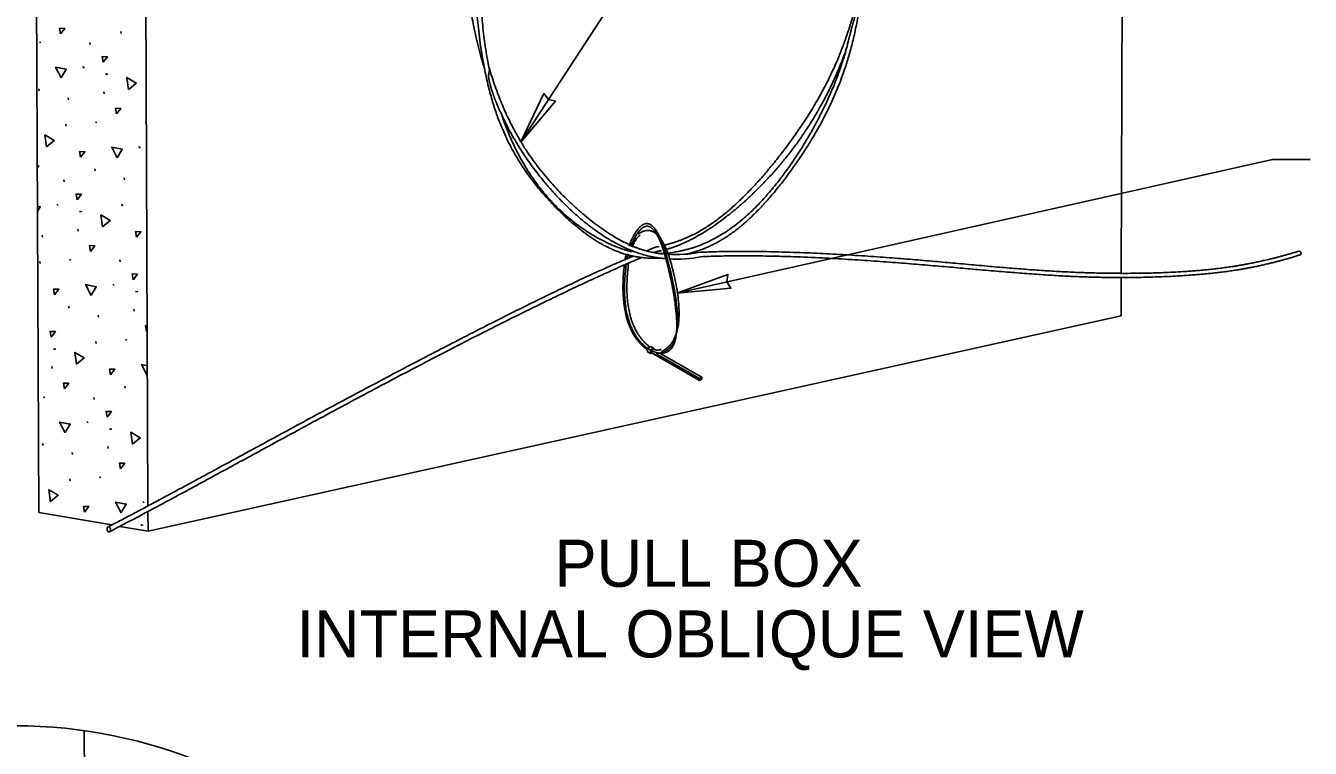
# Model space of a CAD drawing. Extents: x 99862 to 103151, y 100000 to 105076.
# Drawn here: x 101250 to 101795, y 101383 to 101690 of the extents above; entities that cross this region are included whole.
import ezdxf

# ---------------------------------------------------------------- set-up
doc = ezdxf.new("R2010")
doc.units = 0
for name, color, linetype in [('Level 1', 7, 'Continuous'), ('Level 15', 7, 'Continuous'), ('Level 17', 7, 'Continuous'), ('Level 2', 7, 'Continuous'), ('Level 20', 7, 'Continuous'), ('Level 30', 7, 'Continuous'), ('Level 9', 7, 'Continuous')]:
    doc.layers.add(name, color=color, linetype=linetype)

msp = doc.modelspace()

# ---------------------------------------------------------------- linework, layer by layer
at = {"layer": 'Level 1'}
msp.add_line((101274.61, 101299.42), (101274.56, 101390.36), dxfattribs=at)
msp.add_circle((101245.08, 101183.57), 208.77, dxfattribs=at)
at = {"layer": 'Level 15'}
for p, q in [((101459.82, 101640.12), (101521.88, 101735.47)), ((101779.33, 101632.96), (101526.3, 101576.13)), ((101795.33, 101632.96), (101779.33, 101632.96))]:
    msp.add_line(p, q, dxfattribs=at)
for points in [[(101459.82, 101640.12), (101469.77, 101660.88), (101471.69, 101658.36), (101474.77, 101657.62)], [(101526.3, 101576.13), (101549.23, 101578.22), (101547.55, 101580.9), (101547.92, 101584.05)]]:
    msp.add_lwpolyline(points, close=True, dxfattribs=at)
at = {"layer": 'Level 17'}
for p, q in [((101510.64, 101601.75), (101509.64, 101601.18)), ((101510.1, 101600.5), (101510.1, 101600.5)), ((101513.79, 101552.75), (101515.11, 101553.52)), ((101513.79, 101551.22), (101513.79, 101552.75)), ((101515.11, 101551.99), (101513.79, 101552.75)), ((101515.11, 101550.46), (101513.79, 101551.22)), ((101516.44, 101552.75), (101515.11, 101553.52)), ((101515.11, 101551.99), (101516.44, 101552.75)), ((101515.11, 101550.46), (101515.11, 101551.99)), ((101515.61, 101550.74), (101515.11, 101550.46)), ((101515.28, 101551.74), (101516.27, 101552.32)), ((101515.28, 101550.93), (101515.28, 101551.74)), ((101535.83, 101539.07), (101515.28, 101550.93)), ((101516.44, 101552.75), (101516.44, 101552.25)), ((101535.83, 101539.83), (101517.28, 101550.54)), ((101536.82, 101540.41), (101518.8, 101550.81)), ((101519.58, 101551.18), (101520.58, 101551.75)), ((101535.83, 101539.83), (101536.82, 101540.41)), ((101535.83, 101539.07), (101535.83, 101539.83)), ((101536.82, 101539.64), (101535.83, 101539.07)), ((101536.82, 101540.41), (101536.82, 101539.64))]:
    msp.add_line(p, q, dxfattribs=at)
for points in [[(101524.12, 101583.06), (101515.87, 101620.3), (101505.88, 101596.21)], [(101523.48, 101583.22), (101515.98, 101618.07), (101506.62, 101595.94)], [(101510.6, 101600.76), (101508.62, 101599.29), (101507.29, 101595.71)], [(101525.11, 101583.63), (101519.91, 101607.11), (101510.64, 101601.75)], [(101505.22, 101594.41), (101505.18, 101594.28), (101505.14, 101594.14)], [(101505.95, 101594.14), (101505.93, 101594.06), (101505.9, 101593.98)], [(101506.7, 101593.88), (101506.69, 101593.85), (101506.68, 101593.82)], [(101503.96, 101588.23), (101500.87, 101561.65), (101513.79, 101551.87)], [(101504.77, 101588.56), (101501.33, 101562.09), (101513.79, 101552.63)], [(101504.65, 101592.31), (101504.44, 101591.4), (101504.27, 101590.43)], [(101505.74, 101588.97), (101502.45, 101562.83), (101514.69, 101553.27)], [(101505.41, 101592.15), (101505.25, 101591.48), (101505.12, 101590.78)], [(101506.24, 101591.98), (101506.16, 101591.58), (101506.08, 101591.17)], [(101515.28, 101551.74), (101531.72, 101544.62), (101523.48, 101583.22)], [(101517.28, 101550.54), (101531.39, 101550.49), (101524.12, 101583.06)], [(101520.58, 101551.75), (101530.9, 101557.71), (101525.11, 101583.63)], [(101516.27, 101552.32), (101518.02, 101551.56), (101519.63, 101552.24)]]:
    msp.add_open_spline(points, degree=2, dxfattribs=at)
at = {"layer": 'Level 2'}
for p, q in [((101252.49, 102058.09), (101255.28, 101482.88)), ((101301.58, 101485.66), (101299.24, 102058.35)), ((101715.7, 101831.46), (101715.03, 101584.19)), ((101715.02, 101582.43), (101714.98, 101566.54)), ((101714.98, 101566.54), (101301.63, 101475.03)), ((101301.63, 101475.03), (101301.59, 101483.33)), ((101286.23, 101477.64), (101255.28, 101482.88)), ((101301.63, 101475.03), (101289.63, 101477.06))]:
    msp.add_line(p, q, dxfattribs=at)
at = {"layer": 'Level 30'}
for points, degree in [([(101496.76, 101860.97), (101489.22, 101857.41), (101475.08, 101847.32), (101454.44, 101820.1), (101440.55, 101783.63), (101433.45, 101730.23), (101437.88, 101693.33), (101444.56, 101671.4)], 4), ([(101500.41, 101851.5), (101498.68, 101850.1), (101487.39, 101841.27), (101470.38, 101821.19), (101453.25, 101785.1), (101440.55, 101738.77), (101439.71, 101701.95), (101443.1, 101679.69)], 4), ([(101446.53, 101671.57), (101442.22, 101692.95), (101441.48, 101729.1), (101453.52, 101781.74), (101470.66, 101817.94), (101488.3, 101838.79), (101496.84, 101846.14), (101500.94, 101849.56)], 4), ([(101602.08, 101697.49), (101596.55, 101677.42), (101583.66, 101648.28), (101554.67, 101612.16), (101533.92, 101599.62), (101520.38, 101596.35)], 4), ([(101530.45, 101592.7), (101543.36, 101595.94), (101562.84, 101608.14), (101589.37, 101644.32), (101600.09, 101675.12), (101603.78, 101696.76)], 4), ([(101599.17, 101683.48), (101599.27, 101683.88), (101599.37, 101684.29), (101599.62, 101685.3), (101599.78, 101685.91), (101600.25, 101687.72), (101600.57, 101688.93), (101601.06, 101690.75), (101601.23, 101691.35), (101601.59, 101692.55), (101601.78, 101693.15), (101602.13, 101694.02), (101602.26, 101694.3), (101602.56, 101694.85), (101602.75, 101695.11), (101603.13, 101695.58), (101603.33, 101695.79), (101603.61, 101696.22), (101603.71, 101696.45), (101603.79, 101696.79), (101603.8, 101696.86), (101603.81, 101696.94)], 4), ([(101443.02, 101680.23), (101443.11, 101679.6), (101443.21, 101678.96), (101443.52, 101677.05), (101443.76, 101675.79), (101444.1, 101673.92), (101444.21, 101673.3), (101444.37, 101672.4), (101444.42, 101672.11), (101444.51, 101671.63), (101444.55, 101671.43), (101444.6, 101671.24)], 4), ([(101599.22, 101683.69), (101596.79, 101673.62), (101588.58, 101648.69), (101565.57, 101611.58), (101541.21, 101596.6), (101526.92, 101593.87)], 4), ([(101521.33, 101594.63), (101527.42, 101596.14), (101544.55, 101603.1), (101573.28, 101628.29), (101590.9, 101659.89), (101598, 101678.91)], 4), ([(101444.49, 101671.71), (101448.65, 101650.75), (101460.41, 101622.8), (101487.89, 101596.08), (101506.99, 101590.52), (101518.97, 101591.02)], 4), ([(101446.88, 101664.97), (101446.72, 101665.58), (101446.57, 101666.18), (101446.34, 101667.41), (101446.26, 101668.02), (101446.31, 101668.99), (101446.37, 101669.31), (101446.51, 101669.98), (101446.59, 101670.32), (101446.63, 101671), (101446.59, 101671.34), (101446.51, 101671.67)], 4), ([(101520.41, 101592.79), (101511.83, 101593.66), (101495.92, 101599.03), (101468.13, 101622.35), (101452.99, 101650.48), (101446.47, 101671.89)], 4), ([(101448.92, 101658.74), (101448.57, 101659.64), (101448.24, 101660.56), (101447.74, 101662.06), (101447.55, 101662.64), (101447.29, 101663.51), (101447.2, 101663.8), (101447.04, 101664.39), (101446.96, 101664.67), (101446.88, 101664.97)], 4), ([(101448.84, 101658.94), (101452.88, 101648.5), (101465.09, 101624.53), (101490.14, 101598.96), (101511.39, 101591.6), (101521.26, 101590.78)], 4), ([(101507.13, 101593.73), (101506.75, 101593.81), (101495.71, 101595.97), (101473.56, 101608.25), (101457.8, 101634.55), (101451.97, 101651.4)], 4), ([(101517.57, 101595.74), (101516.09, 101595.17), (101514.61, 101594.59), (101513.13, 101594.01)], 3), ([(101516.55, 101593.31), (101517.1, 101593.53), (101517.66, 101593.74), (101518.21, 101593.95)], 3), ([(101518.72, 101595.97), (101518.33, 101595.89), (101517.95, 101595.82), (101517.57, 101595.74)], 3), ([(101518.16, 101593.94), (101518.67, 101594.03), (101519.19, 101594.14), (101519.7, 101594.25)], 3), ([(101520.31, 101593), (101519.91, 101592.97), (101519.52, 101592.95), (101519.12, 101592.93)], 3), ([(101526.92, 101593.87), (101525.29, 101593.55), (101523.66, 101593.31), (101522.04, 101593.15)], 3), ([(101536.29, 101593.5), (101531.64, 101592.61), (101526.95, 101592.32), (101522.26, 101592.64)], 3), ([(101526.92, 101593.87), (101526.92, 101593.87), (101526.92, 101593.87)], 2), ([(101790.44, 101593.96), (101776.12, 101589.58), (101754.4, 101585.46), (101724.44, 101583.99), (101675.4, 101584.69), (101613.67, 101592.75), (101556.78, 101594.44), (101536.29, 101593.5)], 4), ([(101791.38, 101593.06), (101791.38, 101593.36), (101791.25, 101593.66), (101790.86, 101593.97), (101790.63, 101594.02), (101790.44, 101593.96)], 4), ([(101790.91, 101592.32), (101790.95, 101592.33), (101790.99, 101592.35), (101791.24, 101592.49), (101791.38, 101592.76), (101791.38, 101593.06)], 4), ([(101507.49, 101591.75), (101478.35, 101579.88), (101406.43, 101544.16), (101331.01, 101500.72), (101284.6, 101476.8)], 4), ([(101285.27, 101474.8), (101346.72, 101506.52), (101422.23, 101551.63), (101494.64, 101584.54), (101511.31, 101591.23)], 4), ([(101523.06, 101590.66), (101527.54, 101590.43), (101532.02, 101590.74), (101536.45, 101591.59)], 3), ([(101536.45, 101591.59), (101560.02, 101592.7), (101616.78, 101590.37), (101680.51, 101582.59), (101726.57, 101582.26), (101756.45, 101584.09), (101776.31, 101587.85), (101790.91, 101592.32)], 4), ([(101284.56, 101474.95), (101284.33, 101475.18), (101284.18, 101475.56), (101284.18, 101476.29), (101284.32, 101476.62), (101284.77, 101476.92), (101285.08, 101476.86), (101285.53, 101476.42), (101285.68, 101476.04), (101285.68, 101475.67)], 4), ([(101285.68, 101475.67), (101285.68, 101475.3), (101285.54, 101474.97), (101285.09, 101474.68), (101284.79, 101474.73), (101284.56, 101474.95)], 4)]:
    msp.add_open_spline(points, degree=degree, dxfattribs=at)
at = {"layer": 'Level 9'}
for p, q in [((101290.19, 101686.48), (101290.02, 101687.34)), ((101255.48, 101682.78), (101256.08, 101682.55)), ((101277.04, 101681.72), (101276.87, 101682.58)), ((101273.91, 101672.36), (101274.45, 101671.76)), ((101283.51, 101669.23), (101284.11, 101669)), ((101283.92, 101669.27), (101284.51, 101669.04)), ((101255.34, 101662.08), (101255.17, 101662.94)), ((101267.87, 101658.28), (101267.7, 101659.14)), ((101282.99, 101660.83), (101282.82, 101661.69)), ((101266.92, 101647.09), (101266.76, 101647.95)), ((101279.28, 101648.8), (101279.87, 101648.57)), ((101300.83, 101647.74), (101300.67, 101648.6)), ((101297.71, 101638.39), (101298.24, 101637.78)), ((101279.13, 101628.1), (101278.97, 101628.96)), ((101265.99, 101623.34), (101265.82, 101624.2)), ((101291.66, 101624.3), (101291.49, 101625.16)), ((101262.86, 101613.99), (101263.39, 101613.38)), ((101272.46, 101610.85), (101273.05, 101610.62)), ((101272.86, 101610.89), (101273.46, 101610.66)), ((101290.72, 101613.11), (101290.55, 101613.97)), ((101256.82, 101599.9), (101256.65, 101600.76)), ((101271.94, 101602.45), (101271.77, 101603.31)), ((101255.87, 101588.71), (101255.7, 101589.57)), ((101268.22, 101590.42), (101268.82, 101590.19)), ((101289.78, 101589.36), (101289.61, 101590.22)), ((101286.66, 101580.01), (101287.19, 101579.4)), ((101296.25, 101576.87), (101296.85, 101576.64)), ((101296.66, 101576.91), (101297.25, 101576.68)), ((101254.94, 101564.96), (101254.88, 101565.28)), ((101268.08, 101569.72), (101267.91, 101570.58)), ((101280.61, 101565.92), (101280.44, 101566.78)), ((101295.73, 101568.48), (101295.57, 101569.33)), ((101279.66, 101554.73), (101279.5, 101555.59)), ((101292.02, 101556.44), (101292.61, 101556.21)), ((101261.4, 101552.47), (101262, 101552.24)), ((101261.81, 101552.51), (101262.41, 101552.28)), ((101260.89, 101544.08), (101260.72, 101544.93)), ((101291.87, 101535.74), (101291.71, 101536.6)), ((101257.17, 101532.04), (101257.77, 101531.81)), ((101278.73, 101530.99), (101278.56, 101531.84)), ((101275.6, 101521.63), (101276.13, 101521.03)), ((101285.2, 101518.49), (101285.79, 101518.26)), ((101285.6, 101518.53), (101286.2, 101518.3)), ((101257.03, 101511.35), (101256.86, 101512.2)), ((101284.68, 101510.1), (101284.51, 101510.96)), ((101269.56, 101507.54), (101269.39, 101508.4)), ((101268.61, 101496.35), (101268.45, 101497.21)), ((101280.97, 101498.06), (101281.56, 101497.83)), ((101299.4, 101487.65), (101299.93, 101487.05)), ((101298.55, 101477.7), (101299.14, 101477.47)), ((101298.95, 101477.74), (101299.55, 101477.51))]:
    msp.add_line(p, q, dxfattribs=at)
for points in [[(101264.45, 101686.24), (101264.04, 101688.67), (101266.26, 101688.59), (101264.45, 101686.24)], [(101282.53, 101674.19), (101282.13, 101676.62), (101284.35, 101676.54), (101282.53, 101674.19)], [(101264.72, 101667.53), (101262.38, 101672.09), (101266.87, 101671.22), (101264.77, 101667.6)], [(101293.32, 101662.65), (101292.69, 101667.73), (101296.61, 101665.38), (101293.4, 101662.7)], [(101288.24, 101652.26), (101287.84, 101654.69), (101290.06, 101654.61), (101288.24, 101652.26)], [(101258.48, 101638.25), (101257.84, 101643.33), (101261.77, 101640.98), (101258.55, 101638.3)], [(101272.98, 101633.82), (101272.58, 101636.25), (101274.8, 101636.18), (101272.98, 101633.82)], [(101288.51, 101633.55), (101286.18, 101638.11), (101290.66, 101637.24), (101288.56, 101633.62)], [(101254.56, 101630.24), (101255.21, 101630.22), (101254.57, 101629.38)], [(101271.48, 101615.81), (101271.08, 101618.24), (101273.3, 101618.16), (101271.48, 101615.81)], [(101254.64, 101613.07), (101255.82, 101612.84), (101254.66, 101610.84)], [(101282.27, 101604.27), (101281.64, 101609.35), (101285.56, 101607), (101282.34, 101604.32)], [(101296.77, 101599.84), (101296.37, 101602.27), (101298.59, 101602.2), (101296.77, 101599.84)], [(101277.19, 101593.88), (101276.79, 101596.31), (101279, 101596.24), (101277.19, 101593.88)], [(101295.27, 101581.83), (101294.87, 101584.26), (101297.09, 101584.18), (101295.27, 101581.83)], [(101261.93, 101575.45), (101261.53, 101577.88), (101263.75, 101577.8), (101261.93, 101575.45)], [(101277.46, 101575.17), (101275.12, 101579.73), (101279.61, 101578.86), (101277.51, 101575.24)], [(101260.43, 101557.43), (101260.03, 101559.86), (101262.25, 101559.79), (101260.43, 101557.43)], [(101300.98, 101559.9), (101300.58, 101562.33), (101301.27, 101562.31)], [(101301.28, 101560.28), (101300.98, 101559.9)], [(101271.22, 101545.89), (101270.59, 101550.98), (101274.51, 101548.63), (101271.29, 101545.94)], [(101285.72, 101541.47), (101285.32, 101543.9), (101287.54, 101543.82), (101285.72, 101541.47)], [(101301.25, 101541.19), (101298.92, 101545.75), (101301.34, 101545.28)], [(101266.13, 101535.5), (101265.73, 101537.93), (101267.95, 101537.86), (101266.13, 101535.5)], [(101301.35, 101541.35), (101301.3, 101541.26)], [(101284.22, 101523.45), (101283.82, 101525.88), (101286.04, 101525.81), (101284.22, 101523.45)], [(101266.41, 101516.79), (101264.07, 101521.35), (101268.56, 101520.49), (101266.46, 101516.86)], [(101295.01, 101511.91), (101294.38, 101517), (101298.3, 101514.65), (101295.09, 101511.96)], [(101289.93, 101501.52), (101289.53, 101503.95), (101291.75, 101503.88), (101289.93, 101501.52)], [(101260.17, 101487.51), (101259.53, 101492.6), (101263.46, 101490.25), (101260.24, 101487.56)], [(101274.67, 101483.09), (101274.27, 101485.52), (101276.49, 101485.45), (101274.67, 101483.09)], [(101290.2, 101482.81), (101287.86, 101487.37), (101292.35, 101486.51), (101290.25, 101482.88)]]:
    msp.add_lwpolyline(points, dxfattribs=at)

# ---------------------------------------------------------------- texts
at = {"layer": 'Level 20'}
for s, p in [('PULL BOX', (101474.34, 101451.37)), ('INTERNAL OBLIQUE VIEW', (101364.73, 101421.37))]:
    msp.add_text(s, height=20, dxfattribs=at).set_placement(p)

doc.saveas('drawing.dxf')
